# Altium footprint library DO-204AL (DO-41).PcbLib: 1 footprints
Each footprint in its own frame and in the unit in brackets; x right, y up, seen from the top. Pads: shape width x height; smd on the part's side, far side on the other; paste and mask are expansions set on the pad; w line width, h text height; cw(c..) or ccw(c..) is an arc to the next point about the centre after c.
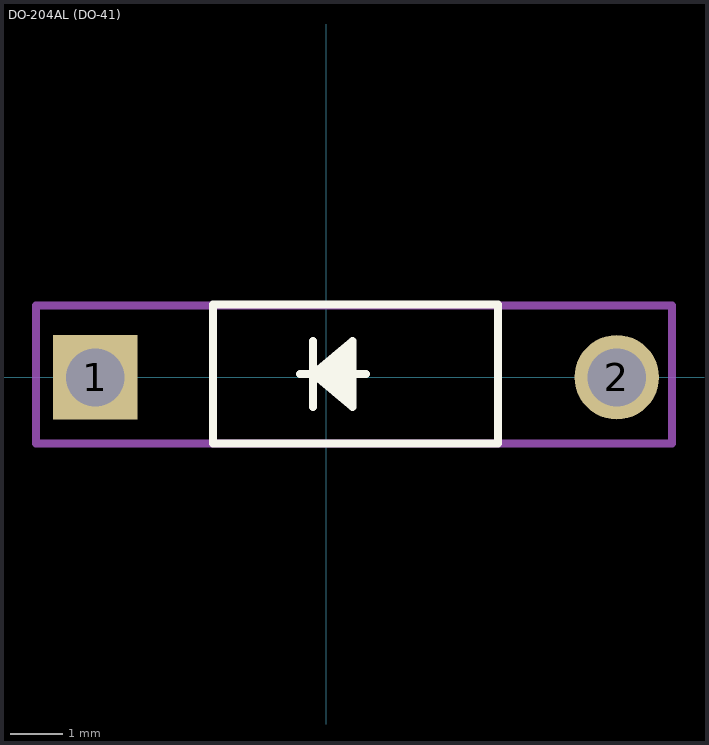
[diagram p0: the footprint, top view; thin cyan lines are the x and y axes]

## DO-204AL (DO-41) [mil]
pads (2):
  rect 64x64 hole 44: 1(-175,0)
  round 64 hole 44: 2(220,0)
Top Overlay:
  lines w6: -20,2.5 30,2.5 ; -10,-22.5 -10,27.5 ; 20,-17.5 -10,2.5 ; 20,-12.5 -10,2.5 ; 20,-7.5 -10,2.5 ; 20,-2.5 -10,2.5 ; 20,7.5 -10,2.5 ; 20,12.5 -10,2.5 ; 20,17.5 -10,2.5 ; 20,22.5 -10,2.5 ; -10,2.5 20,27.5 20,-22.5 -10,2.5 ; -85.71,-50 130,-50 130,55 -85.71,55 -85.71,-50
Mechanical 15:
  lines w6: -220,-50 -220,54.49 -90.71,54.49 90.71,54.49 262,54.49 262,-50 90.71,-50 -90.71,-50 -220,-50
3D body "User Library-DO-41-3.STEP": height 131.89, standoff -78.74, extent -196.93,-52.76 236.93,52.76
